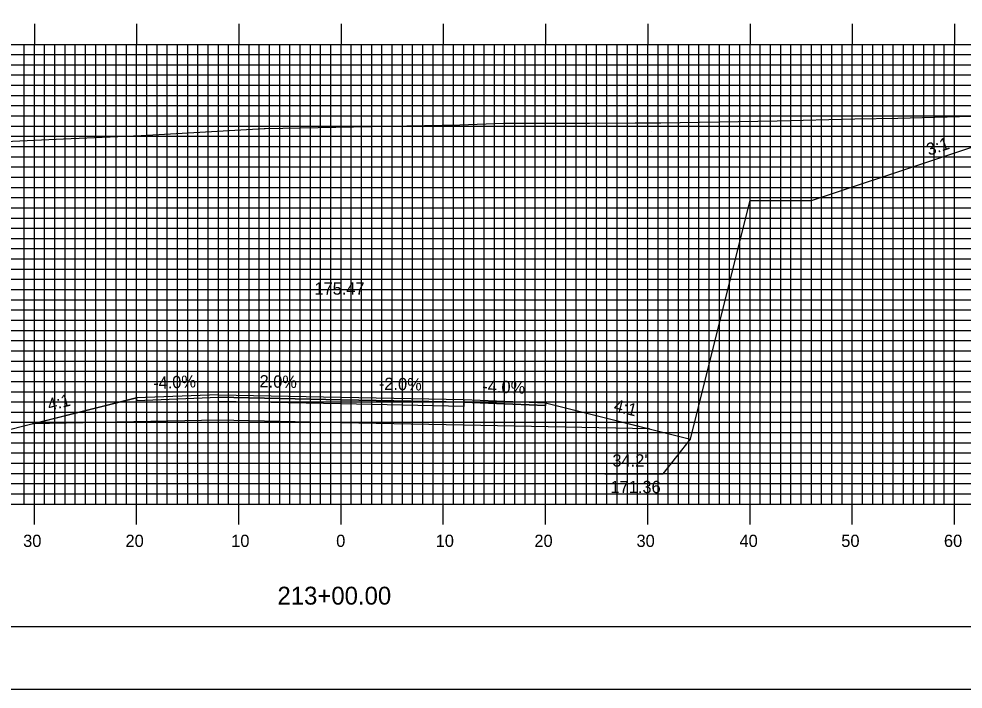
# Model space of a CAD drawing. Extents: x 1795633 to 1795976, y 442591 to 442811.
# Drawn here: x 1795767.4 to 1795859.7, y 442590.5 to 442656.2 of the extents above; entities that cross this region are included whole.
import ezdxf

# ---------------------------------------------------------------- set-up
doc = ezdxf.new("R2010")
doc.units = 0
for name, color, linetype in [('ANNOTATION', 7, 'Continuous'), ('BORDER', 7, 'Continuous'), ('D_Roadway_Centerline', 7, 'Continuous'), ('D_Roadway_Centerline_Text', 7, 'Continuous'), ('D_Roadway_Edge_Shoulder', 7, 'Continuous'), ('D_Roadway_Edge_TW', 7, 'Continuous'), ('D_Roadway_Pavement', 7, 'Continuous'), ('D_Roadway_SlopeLines', 7, 'Continuous'), ('D_Roadway_SubGrade', 7, 'Continuous'), ('H_V ANNOTATION', 7, 'Continuous'), ('MAJOR', 7, 'Continuous'), ('MINOR', 7, 'Continuous'), ('PLOT BOUNDARY', 7, 'Continuous'), ('S_Property_Well_GroundElevation', 7, 'Continuous'), ('S_Roadway_Centerline', 7, 'Continuous')]:
    doc.layers.add(name, color=color, linetype=linetype)

msp = doc.modelspace()

# ---------------------------------------------------------------- linework, layer by layer
at = {"layer": 'ANNOTATION'}
msp.add_lwpolyline([(1795824.685, 442611.61), (1795830.377, 442611.61), (1795833.053, 442615.027)], dxfattribs=at)
at = {"layer": 'BORDER'}
msp.add_lwpolyline([(1795649.279, 442596.665), (1795969.279, 442596.665), (1795969.279, 442806.665), (1795649.279, 442806.665)], close=True, dxfattribs=at)
at = {"layer": 'D_Roadway_Edge_Shoulder'}
for points in [[(1795786.879, 442619.37), (1795778.879, 442619.05), (1795778.879, 442618.8), (1795786.879, 442619.12)], [(1795810.879, 442618.89), (1795818.879, 442618.57), (1795818.879, 442618.32), (1795810.879, 442618.64)]]:
    msp.add_lwpolyline(points, close=True, dxfattribs=at)
at = {"layer": 'D_Roadway_Edge_TW'}
msp.add_lwpolyline([(1795786.879, 442619.12), (1795786.879, 442619.37), (1795798.879, 442619.13), (1795810.879, 442618.89), (1795810.879, 442618.64), (1795798.879, 442618.88)], close=True, dxfattribs=at)
at = {"layer": 'D_Roadway_Pavement'}
msp.add_lwpolyline([(1795786.879, 442618.704), (1795786.879, 442619.12), (1795798.879, 442618.88), (1795810.879, 442618.64), (1795810.879, 442618.224), (1795798.879, 442618.464)], close=True, dxfattribs=at)
at = {"layer": 'D_Roadway_SlopeLines'}
for p, q in [((1795837.137, 442631.361), (1795838.888, 442638.365)), ((1795833.053, 442615.027), (1795837.137, 442631.361))]:
    msp.add_line(p, q, dxfattribs=at)
for points in [[(1795838.888, 442638.365), (1795844.888, 442638.365), (1795868.728, 442646.312)], [(1795778.879, 442619.05), (1795764.705, 442615.507)], [(1795818.879, 442618.57), (1795833.053, 442615.027)]]:
    msp.add_lwpolyline(points, dxfattribs=at)
at = {"layer": 'D_Roadway_SubGrade'}
msp.add_lwpolyline([(1795786.879, 442616.87), (1795768.705, 442616.507), (1795778.879, 442619.05), (1795778.879, 442618.8), (1795786.879, 442619.12), (1795798.879, 442618.88), (1795810.879, 442618.64), (1795818.879, 442618.32), (1795818.879, 442618.57), (1795829.053, 442616.027), (1795810.879, 442616.39), (1795798.879, 442616.63)], close=True, dxfattribs=at)
at = {"layer": 'MAJOR'}
for p, q in [((1795768.879, 442655.669), (1795768.879, 442653.665)), ((1795778.879, 442655.669), (1795778.879, 442653.665)), ((1795788.879, 442655.669), (1795788.879, 442653.665)), ((1795798.879, 442655.669), (1795798.879, 442653.665)), ((1795808.879, 442655.669), (1795808.879, 442653.665)), ((1795818.879, 442655.669), (1795818.879, 442653.665)), ((1795828.879, 442655.669), (1795828.879, 442653.665)), ((1795838.879, 442655.669), (1795838.879, 442653.665)), ((1795848.879, 442655.669), (1795848.879, 442653.665)), ((1795858.879, 442655.669), (1795858.879, 442653.665)), ((1795658.879, 442653.665), (1795938.879, 442653.665)), ((1795658.879, 442653.665), (1795938.879, 442653.665)), ((1795768.879, 442608.665), (1795768.879, 442653.665)), ((1795778.879, 442608.665), (1795778.879, 442653.665)), ((1795788.879, 442608.665), (1795788.879, 442653.665)), ((1795798.879, 442608.665), (1795798.879, 442653.665)), ((1795808.879, 442608.665), (1795808.879, 442653.665)), ((1795818.879, 442608.665), (1795818.879, 442653.665)), ((1795828.879, 442608.665), (1795828.879, 442653.665)), ((1795838.879, 442608.665), (1795838.879, 442653.665)), ((1795848.879, 442608.665), (1795848.879, 442653.665)), ((1795858.879, 442608.665), (1795858.879, 442653.665)), ((1795658.879, 442648.665), (1795938.879, 442648.665)), ((1795658.879, 442643.665), (1795938.879, 442643.665)), ((1795658.879, 442638.665), (1795938.879, 442638.665)), ((1795658.879, 442633.665), (1795938.879, 442633.665)), ((1795658.879, 442628.665), (1795938.879, 442628.665)), ((1795658.879, 442623.665), (1795938.879, 442623.665)), ((1795658.879, 442618.665), (1795938.879, 442618.665)), ((1795658.879, 442613.665), (1795938.879, 442613.665)), ((1795658.879, 442608.665), (1795938.879, 442608.665)), ((1795658.879, 442608.665), (1795938.879, 442608.665)), ((1795768.879, 442606.661), (1795768.879, 442608.665)), ((1795778.879, 442606.661), (1795778.879, 442608.665)), ((1795788.879, 442606.661), (1795788.879, 442608.665)), ((1795798.879, 442606.661), (1795798.879, 442608.665)), ((1795808.879, 442606.661), (1795808.879, 442608.665)), ((1795818.879, 442606.661), (1795818.879, 442608.665)), ((1795828.879, 442606.661), (1795828.879, 442608.665)), ((1795838.879, 442606.661), (1795838.879, 442608.665)), ((1795848.879, 442606.661), (1795848.879, 442608.665)), ((1795858.879, 442606.661), (1795858.879, 442608.665))]:
    msp.add_line(p, q, dxfattribs=at)
at = {"layer": 'MINOR'}
for p, q in [((1795767.879, 442608.665), (1795767.879, 442653.665)), ((1795769.879, 442608.665), (1795769.879, 442653.665)), ((1795770.879, 442608.665), (1795770.879, 442653.665)), ((1795771.879, 442608.665), (1795771.879, 442653.665)), ((1795772.879, 442608.665), (1795772.879, 442653.665)), ((1795773.879, 442608.665), (1795773.879, 442653.665)), ((1795774.879, 442608.665), (1795774.879, 442653.665)), ((1795775.879, 442608.665), (1795775.879, 442653.665)), ((1795776.879, 442608.665), (1795776.879, 442653.665)), ((1795777.879, 442608.665), (1795777.879, 442653.665)), ((1795779.879, 442608.665), (1795779.879, 442653.665)), ((1795780.879, 442608.665), (1795780.879, 442653.665)), ((1795781.879, 442608.665), (1795781.879, 442653.665)), ((1795782.879, 442608.665), (1795782.879, 442653.665)), ((1795783.879, 442608.665), (1795783.879, 442653.665)), ((1795784.879, 442608.665), (1795784.879, 442653.665)), ((1795785.879, 442608.665), (1795785.879, 442653.665)), ((1795786.879, 442608.665), (1795786.879, 442653.665)), ((1795787.879, 442608.665), (1795787.879, 442653.665)), ((1795789.879, 442608.665), (1795789.879, 442653.665)), ((1795790.879, 442608.665), (1795790.879, 442653.665)), ((1795791.879, 442608.665), (1795791.879, 442653.665)), ((1795792.879, 442608.665), (1795792.879, 442653.665)), ((1795793.879, 442608.665), (1795793.879, 442653.665)), ((1795794.879, 442608.665), (1795794.879, 442653.665)), ((1795795.879, 442608.665), (1795795.879, 442653.665)), ((1795796.879, 442608.665), (1795796.879, 442653.665)), ((1795797.879, 442608.665), (1795797.879, 442653.665)), ((1795799.879, 442608.665), (1795799.879, 442653.665)), ((1795800.879, 442608.665), (1795800.879, 442653.665)), ((1795801.879, 442608.665), (1795801.879, 442653.665)), ((1795802.879, 442608.665), (1795802.879, 442653.665)), ((1795803.879, 442608.665), (1795803.879, 442653.665)), ((1795804.879, 442608.665), (1795804.879, 442653.665)), ((1795805.879, 442608.665), (1795805.879, 442653.665)), ((1795806.879, 442608.665), (1795806.879, 442653.665)), ((1795807.879, 442608.665), (1795807.879, 442653.665)), ((1795809.879, 442608.665), (1795809.879, 442653.665)), ((1795810.879, 442608.665), (1795810.879, 442653.665)), ((1795811.879, 442608.665), (1795811.879, 442653.665)), ((1795812.879, 442608.665), (1795812.879, 442653.665)), ((1795813.879, 442608.665), (1795813.879, 442653.665)), ((1795814.879, 442608.665), (1795814.879, 442653.665)), ((1795815.879, 442608.665), (1795815.879, 442653.665)), ((1795816.879, 442608.665), (1795816.879, 442653.665)), ((1795817.879, 442608.665), (1795817.879, 442653.665)), ((1795819.879, 442608.665), (1795819.879, 442653.665)), ((1795820.879, 442608.665), (1795820.879, 442653.665)), ((1795821.879, 442608.665), (1795821.879, 442653.665)), ((1795822.879, 442608.665), (1795822.879, 442653.665)), ((1795823.879, 442608.665), (1795823.879, 442653.665)), ((1795824.879, 442608.665), (1795824.879, 442653.665)), ((1795825.879, 442608.665), (1795825.879, 442653.665)), ((1795826.879, 442608.665), (1795826.879, 442653.665)), ((1795827.879, 442608.665), (1795827.879, 442653.665)), ((1795829.879, 442608.665), (1795829.879, 442653.665)), ((1795830.879, 442608.665), (1795830.879, 442653.665)), ((1795831.879, 442608.665), (1795831.879, 442653.665)), ((1795832.879, 442608.665), (1795832.879, 442653.665)), ((1795833.879, 442608.665), (1795833.879, 442653.665)), ((1795834.879, 442608.665), (1795834.879, 442653.665)), ((1795835.879, 442608.665), (1795835.879, 442653.665)), ((1795836.879, 442608.665), (1795836.879, 442653.665)), ((1795837.879, 442608.665), (1795837.879, 442653.665)), ((1795839.879, 442608.665), (1795839.879, 442653.665)), ((1795840.879, 442608.665), (1795840.879, 442653.665)), ((1795841.879, 442608.665), (1795841.879, 442653.665)), ((1795842.879, 442608.665), (1795842.879, 442653.665)), ((1795843.879, 442608.665), (1795843.879, 442653.665)), ((1795844.879, 442608.665), (1795844.879, 442653.665)), ((1795845.879, 442608.665), (1795845.879, 442653.665)), ((1795846.879, 442608.665), (1795846.879, 442653.665)), ((1795847.879, 442608.665), (1795847.879, 442653.665)), ((1795849.879, 442608.665), (1795849.879, 442653.665)), ((1795850.879, 442608.665), (1795850.879, 442653.665)), ((1795851.879, 442608.665), (1795851.879, 442653.665)), ((1795852.879, 442608.665), (1795852.879, 442653.665)), ((1795853.879, 442608.665), (1795853.879, 442653.665)), ((1795854.879, 442608.665), (1795854.879, 442653.665)), ((1795855.879, 442608.665), (1795855.879, 442653.665)), ((1795856.879, 442608.665), (1795856.879, 442653.665)), ((1795857.879, 442608.665), (1795857.879, 442653.665)), ((1795658.879, 442652.665), (1795938.879, 442652.665)), ((1795658.879, 442651.665), (1795938.879, 442651.665)), ((1795658.879, 442650.665), (1795938.879, 442650.665)), ((1795658.879, 442649.665), (1795938.879, 442649.665)), ((1795658.879, 442647.665), (1795938.879, 442647.665)), ((1795658.879, 442646.665), (1795938.879, 442646.665)), ((1795658.879, 442645.665), (1795938.879, 442645.665)), ((1795658.879, 442644.665), (1795938.879, 442644.665)), ((1795658.879, 442642.665), (1795938.879, 442642.665)), ((1795658.879, 442641.665), (1795938.879, 442641.665)), ((1795658.879, 442640.665), (1795938.879, 442640.665)), ((1795658.879, 442639.665), (1795938.879, 442639.665)), ((1795658.879, 442637.665), (1795938.879, 442637.665)), ((1795658.879, 442636.665), (1795938.879, 442636.665)), ((1795658.879, 442635.665), (1795938.879, 442635.665)), ((1795658.879, 442634.665), (1795938.879, 442634.665)), ((1795658.879, 442632.665), (1795938.879, 442632.665)), ((1795658.879, 442631.665), (1795938.879, 442631.665)), ((1795658.879, 442630.665), (1795938.879, 442630.665)), ((1795658.879, 442629.665), (1795938.879, 442629.665)), ((1795658.879, 442627.665), (1795938.879, 442627.665)), ((1795658.879, 442626.665), (1795938.879, 442626.665)), ((1795658.879, 442625.665), (1795938.879, 442625.665)), ((1795658.879, 442624.665), (1795938.879, 442624.665)), ((1795658.879, 442622.665), (1795938.879, 442622.665)), ((1795658.879, 442621.665), (1795938.879, 442621.665)), ((1795658.879, 442620.665), (1795938.879, 442620.665)), ((1795658.879, 442619.665), (1795938.879, 442619.665)), ((1795658.879, 442617.665), (1795938.879, 442617.665)), ((1795658.879, 442616.665), (1795938.879, 442616.665)), ((1795658.879, 442615.665), (1795938.879, 442615.665)), ((1795658.879, 442614.665), (1795938.879, 442614.665)), ((1795658.879, 442612.665), (1795938.879, 442612.665)), ((1795658.879, 442611.665), (1795938.879, 442611.665)), ((1795658.879, 442610.665), (1795938.879, 442610.665)), ((1795658.879, 442609.665), (1795938.879, 442609.665))]:
    msp.add_line(p, q, dxfattribs=at)
at = {"layer": 'PLOT BOUNDARY'}
msp.add_lwpolyline([(1795633.092, 442590.547), (1795973.092, 442590.547), (1795973.092, 442810.547), (1795633.092, 442810.547)], close=True, dxfattribs=at)
at = {"layer": 'S_Property_Well_GroundElevation'}
for p, q in [((1795829.253, 442645.104), (1795829.25, 442645.104)), ((1795829.251, 442645.105), (1795829.251, 442645.103)), ((1795829.252, 442645.103), (1795829.251, 442645.105)), ((1795829.252, 442645.105), (1795829.251, 442645.103))]:
    msp.add_line(p, q, dxfattribs=at)
at = {"layer": 'S_Roadway_Centerline'}
msp.add_lwpolyline([(1795703.44, 442641.209), (1795721.553, 442641.975), (1795728.975, 442642.255), (1795733.766, 442642.477), (1795741.468, 442642.963), (1795752.624, 442643.595), (1795759.475, 442643.964), (1795766.73, 442644.174), (1795771.712, 442644.431), (1795779.336, 442644.754), (1795791.365, 442645.425), (1795791.458, 442645.427), (1795810.49, 442645.796), (1795814.769, 442645.964), (1795823.19, 442645.949), (1795827.655, 442645.966), (1795830.161, 442645.986), (1795841.531, 442646.19), (1795849.119, 442646.362), (1795853.354, 442646.443), (1795862.992, 442646.707)], dxfattribs=at)

# ---------------------------------------------------------------- texts
at = {"layer": 'ANNOTATION'}
for s, rotation, p in [('3:1', 18.71551, (1795856.382, 442642.754)), ('3:1', 18.71551, (1795856.382, 442642.754)), ('-4.0%', 2.29061, (1795780.511, 442619.917)), ('2.0%', 358.85424, (1795790.886, 442620.091)), ('-2.0%', 358.85424, (1795802.565, 442619.857)), ('-4.0%', 357.70939, (1795812.671, 442619.62)), ('4:1', 14.03624, (1795770.328, 442617.774)), ('4:1', 345.96376, (1795825.472, 442617.784))]:
    msp.add_text(s, height=1.2, rotation=rotation, dxfattribs=at).set_placement(p)
for s, p in [("34.2'", (1795825.42, 442612.336)), ('171.36', (1795825.232, 442609.736))]:
    msp.add_text(s, height=1.2, dxfattribs=at).set_placement(p)
at = {"layer": 'D_Roadway_Centerline'}
for s, p in [('C', (1795798.874, 442619.13)), ('L', (1795798.879, 442619.123))]:
    msp.add_text(s, height=0.0146, dxfattribs=at).set_placement(p)
at = {"layer": 'D_Roadway_Centerline_Text'}
msp.add_text('175.47', height=1.2, dxfattribs=at).set_placement((1795796.268, 442629.16))
at = {"layer": 'H_V ANNOTATION'}
for s, height, p in [('30', 1.2, (1795767.776, 442604.465)), ('20', 1.2, (1795777.787, 442604.465)), ('10', 1.2, (1795788.13, 442604.465)), ('0', 1.2, (1795798.397, 442604.465)), ('10', 1.2, (1795808.13, 442604.465)), ('20', 1.2, (1795817.787, 442604.465)), ('30', 1.2, (1795827.776, 442604.465)), ('40', 1.2, (1795837.851, 442604.465)), ('50', 1.2, (1795847.808, 442604.465)), ('60', 1.2, (1795857.851, 442604.465)), ('213+00.00', 1.75, (1795792.652, 442598.821))]:
    msp.add_text(s, height=height, dxfattribs=at).set_placement(p)
at = {"layer": 'S_Property_Well_GroundElevation'}
msp.add_text('WG', height=0.00583, dxfattribs=at).set_placement((1795829.247, 442645.095))

doc.saveas('drawing.dxf')
